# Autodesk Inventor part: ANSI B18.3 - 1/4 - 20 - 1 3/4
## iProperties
Comments: To add or edit properties for Autodesk Inventor files, use iProperties.
Created: 2005-05
Part Number: ANSI B18.3 - 1/4 - 20 - 1 3/4
Vendor: Autodesk Inc.
Document SubType Name: Modeling
Designer: John Blackburn
Material: Default
Description: Hexagon Socket Head Cap Screw
Standard: ANSI B18.3
Alert: To add or edit properties for Autodesk Inventor files, use iProperties.
Control State: 0
Master: False
Checked Out: False
Shininess: 64.0
Length Units: 11272
Angle Units: 11279
Time Units: 11290
Mass Units: 11286
Length Display Precision: 3
Angle Display Precision: 2
Compacted: True
EGR: 3
Classification: un/spsc 31161501
Density: 0.0
Volumn: 0.0
Area: 0.0
PropertySet Name: Model Information
Author: John Blackburn
Revision Number: 8
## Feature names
1. Body [Revolution]
2. Slot [Extrusion]
3. Fillet1
4. Chamfer1
